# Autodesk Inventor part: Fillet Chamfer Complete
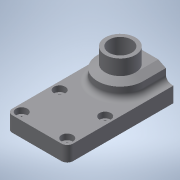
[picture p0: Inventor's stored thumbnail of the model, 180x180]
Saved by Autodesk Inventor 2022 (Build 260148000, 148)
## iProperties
Created: 2013-12
Part Number: Fillet Chamfer Complete
Material: Generic
Document SubType Name: Modeling
Designer: John
Density: 1 g/cm^3
Appearance: Default
Author: John
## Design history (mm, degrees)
sketch "Sketch1"
  geometry: L1 (0, 0)-(-50.8, 0); L2 (-50.8, 0)-(-50.8, -88.9); L3 (-50.8, -88.9)-(0, -88.9); L4 (0, -88.9)-(0, 0)
  constraints: 8 end point, 2 parallel, 1 horizontal, 1 perpendicular
  dimensions: "d0" = 50.8 distance of L3.end L2.end; "d1" = 88.9 distance of L2.end L1.end
extrude "Extrusion1" new body sketch "Sketch1" distance "d2" = 12.7; taper "d3" = 0 deg
sketch "Sketch2"
  geometry: L1 (50.8, 0)-(50.8, 88.9) reference; L2 (50.8, 88.9)-(0, 88.9) reference; L3 (0, 88.9)-(0, 0) reference; L4 (6.35, 88.9)-(44.45, 88.9); L5 (44.45, 88.9)-(44.45, 69.85); L6 (44.45, 69.85)-(6.35, 69.85); L7 (6.35, 69.85)-(6.35, 88.9); L8 (6.35, 79.375)-(0, 79.375); L9 (44.45, 79.375)-(50.8, 79.375); 1 further point
  constraints: 12 end point, 3 midpoint, 3 perpendicular, 3 point on line, 2 parallel, 1 collinear, 1 horizontal, 1 horizontal alignment, 2 other
  dimensions: "d4" = 19.05 distance of L4.end L5.end; "d5" = 6.35 distance between parallel lines of L3 L7
extrude "Extrusion2" join sketch "Sketch2" distance "d6" = 12.7; taper "d7" = 0 deg
sketch "Sketch3"
  geometry: C1 r 12.7 at (25.4, 69.85); A1 r 19.05 centre (25.4, 69.85) between (6.35, 69.85) and (44.45, 69.85) reference; 1 further point
  constraints: 1 centre point, 1 coincident
  dimensions: "d8" = 25.4 diameter of C1
extrude "Extrusion3" join sketch "Sketch3" distance "d9" = 12.7; taper "d10" = 0 deg
sketch "Sketch6"
  geometry: L1 (0, 88.9)-(0, 0) reference; L2 (0, 0)-(50.8, 0) reference; L3 (50.8, 0)-(50.8, 88.9) reference; L4 (44.45, 88.9)-(44.45, 6.35); L5 (44.45, 6.35)-(6.35, 6.35); L6 (6.35, 6.35)-(6.35, 88.9); L7 (6.35, 38.1)-(44.45, 38.1)
  constraints: 8 end point, 2 point on line, 1 perpendicular, 2 other
  dimensions: "d35" = 6.35 distance between parallel lines of L2 L5; "d36" = 31.75 distance between parallel lines of L5 L7
hole "Hole3" diameter "d39" = 19.05; stored, may be unused: countersink angle "d43" = 82 deg, drill point angle "d45" = 118 deg; dims "d37" = 25.4, "d38" = 25.4, "d40" = 19.05, "d41" = 9.525, "d42" = 6.35, "d44" = 25.4
sketch "Sketch7"
  geometry: L1 (0, 0)-(0, 12.7) reference; L2 (44.45, 12.7)-(6.35, 12.7); 1 further point
  constraints: 2 end point, 1 midpoint, 1 perpendicular
hole "Hole4" sketch "Sketch7" at (25.4, 12.7) diameter "d46" = 4.9784; stored, may be unused: countersink angle "d50" = 82 deg, drill point angle "d52" = 118 deg; dims "d47" = 19.05, "d48" = 9.525, "d49" = 6.35, "d51" = 25.4
hole "Hole5" sketch "Sketch6" diameter "d53" = 5.1054; stored, may be unused: countersink angle "d57" = 82 deg, drill point angle "d59" = 118 deg; dims "d54" = 19.05, "d55" = 9.525, "d56" = 4.826, "d58" = 25.4
fillet "Fillet1" dims "d60" = 4.7625
chamfer "Chamfer1" distance "d61" = 6.35; stored, may be unused: second distance "d62" = 3.175, angle "d63" = 45 deg
body "Solid1"
